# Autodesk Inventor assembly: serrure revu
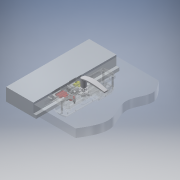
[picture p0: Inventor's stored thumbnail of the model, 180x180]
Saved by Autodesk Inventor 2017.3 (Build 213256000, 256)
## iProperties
Created: 2011-01
Part Number: serrure revu
Material: Générique
Document SubType Name: Assembly
Designer: ficho
Sending System: SolidWorks 2009
Last Author: christophe
Last Saved: 2011-02-11
Author: ficho
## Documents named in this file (12)
- G:\travail\année 2019-2020\réforme\toussaint\Serrure biométrique SET\Documentations_pedagogique\Modelisation_Solidworks\serrure revu.iam
- G:\travail\année 2019-2020\réforme\toussaint\Serrure biométrique SET\Documentations_pedagogique\Modelisation_Solidworks\porte.iam
- G:\travail\année 2019-2020\réforme\toussaint\Serrure biométrique SET\Documentations_pedagogique\Modelisation_Solidworks\poignee interieure.iam
- G:\travail\année 2019-2020\réforme\toussaint\Serrure biométrique SET\Documentations_pedagogique\Modelisation_Solidworks\axe de noix.ipt
- G:\travail\année 2019-2020\réforme\toussaint\Serrure biométrique SET\Documentations_pedagogique\Modelisation_Solidworks\verrouilleur.ipt
- G:\travail\année 2019-2020\réforme\toussaint\Serrure biométrique SET\Documentations_pedagogique\Modelisation_Solidworks\axe moteur.ipt
- G:\travail\année 2019-2020\réforme\toussaint\Serrure biométrique SET\Documentations_pedagogique\Modelisation_Solidworks\plaque.iam
- G:\travail\année 2019-2020\réforme\toussaint\Serrure biométrique SET\Documentations_pedagogique\Modelisation_Solidworks\pene dormant.iam
- G:\travail\année 2019-2020\réforme\toussaint\Serrure biométrique SET\Documentations_pedagogique\Modelisation_Solidworks\pene lançant.iam
- G:\travail\année 2019-2020\réforme\toussaint\Serrure biométrique SET\Documentations_pedagogique\Modelisation_Solidworks\poussoir.ipt
- G:\travail\année 2019-2020\réforme\toussaint\Serrure biométrique SET\Documentations_pedagogique\Modelisation_Solidworks\guide ressort.ipt
- G:\travail\année 2019-2020\réforme\toussaint\Serrure biométrique SET\Documentations_pedagogique\Modelisation_Solidworks\chambranle.iam
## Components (11 placed, 11 different names)
1. porte:1 [sub-assembly] — Placage:1, Placage:2, Placage:3, Angle:1, Tangente:1, Tangente:2, Tangente:3, Placage:4, Placage:5, Placage:6, Placage:7, Tangente:4, Angle:2
2. poignee interieure:1 [sub-assembly] — Placage:1, Placage:2
3. axe de noix:1
4. verrouilleur:1 — Placage:5, Placage:6
5. axe moteur:1
6. plaque:1 [sub-assembly] — Tangente:2, Tangente:3, Placage:4, Tangente:5
7. pene dormant:1 [sub-assembly] — Placage:7, Tangente:4, Angle:2, Tangente:5
8. pene lançant:1 [sub-assembly] — Placage:3, Angle:1, Tangente:1
9. poussoir:1
10. guide ressort:1
11. chambranle:1 [sub-assembly]
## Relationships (14: Mate 7, Tangent 5, Angle 2)
- Placage:1 [Mate]: porte:1 ↔ poignee interieure:1
- Placage:2 [Mate]: porte:1 ↔ poignee interieure:1
- Placage:3 [Mate]: porte:1 ↔ pene lançant:1
- Angle:1: porte:1 ↔ pene lançant:1
- Tangente:1: porte:1 ↔ pene lançant:1
- Tangente:2: porte:1 ↔ plaque:1
- Tangente:3: porte:1 ↔ plaque:1
- Placage:4 [Mate]: porte:1 ↔ plaque:1
- Placage:5 [Mate]: porte:1 ↔ verrouilleur:1
- Placage:6 [Mate]: porte:1 ↔ verrouilleur:1
- Placage:7 [Mate]: porte:1 ↔ pene dormant:1
- Tangente:4: porte:1 ↔ pene dormant:1
- Angle:2: porte:1 ↔ pene dormant:1
- Tangente:5: plaque:1 ↔ pene dormant:1
